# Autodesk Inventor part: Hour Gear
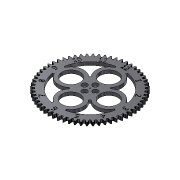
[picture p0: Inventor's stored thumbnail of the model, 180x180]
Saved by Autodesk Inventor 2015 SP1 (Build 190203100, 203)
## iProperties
Created: 2015-01
Part Number: Hour Gear
Material: Generic
Document SubType Name: Modeling
Designer: Steve Brooks
Density: 1 g/cm^3
Appearance: Machined 02
Author: Steve Brooks
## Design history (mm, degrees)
sketch "Sketch1"
  geometry: L1 (188.518, 97.087)-(187.786, 96.937); L2 (187.786, 96.937)-(187.059, 96.777); L3 (187.059, 96.777)-(183.576, 103.613); L4 (183.576, 103.613)-(184.133, 104.108); L5 (184.133, 104.108)-(184.684, 104.611); L6 (184.684, 104.611)-(185.773, 105.645); L7 (185.773, 105.645)-(187.893, 107.812); L8 (187.893, 107.812)-(189.944, 110.099); L9 (189.944, 110.099)-(191.929, 112.496); L10 (191.929, 112.496)-(193.85, 114.995); L11 (193.85, 114.995)-(195.708, 117.588); L12 (195.708, 117.588)-(194.272, 120.077); L13 (194.272, 120.077)-(191.096, 119.764); L14 (191.096, 119.764)-(187.971, 119.349); L15 (187.971, 119.349)-(184.903, 118.829); L16 (184.903, 118.829)-(181.898, 118.197); L17 (181.898, 118.197)-(178.96, 117.444); L18 (178.96, 117.444)-(177.52, 117.019); L19 (177.52, 117.019)-(176.809, 116.792); L20 (176.809, 116.792)-(176.102, 116.557); L21 (176.102, 116.557)-(171.923, 122.992); L22 (171.923, 122.992)-(172.426, 123.542); L23 (172.426, 123.542)-(172.922, 124.1); L24 (172.922, 124.1)-(173.896, 125.242); L25 (173.896, 125.242)-(175.778, 127.619); L26 (175.778, 127.619)-(177.579, 130.108); L27 (177.579, 130.108)-(179.302, 132.699); L28 (179.302, 132.699)-(180.951, 135.385); L29 (180.951, 135.385)-(182.529, 138.159); L30 (182.529, 138.159)-(180.84, 140.483); L31 (180.84, 140.483)-(177.714, 139.841); L32 (177.714, 139.841)-(174.651, 139.101); L33 (174.651, 139.101)-(171.654, 138.263); L34 (171.654, 138.263)-(168.73, 137.321); L35 (168.73, 137.321)-(165.888, 136.265); L36 (165.888, 136.265)-(164.501, 135.691); L37 (164.501, 135.691)-(163.816, 135.392); L38 (163.816, 135.392)-(163.138, 135.084); L39 (163.138, 135.084)-(158.309, 141.047); L40 (158.309, 141.047)-(158.752, 141.646); L41 (158.752, 141.646)-(159.187, 142.253); L42 (159.187, 142.253)-(160.037, 143.49); L43 (160.037, 143.49)-(161.66, 146.052); L44 (161.66, 146.052)-(163.19, 148.715); L45 (163.19, 148.715)-(164.633, 151.473); L46 (164.633, 151.473)-(165.993, 154.316); L47 (165.993, 154.316)-(167.271, 157.239); L48 (167.271, 157.239)-(165.35, 159.375); L49 (165.35, 159.375)-(162.307, 158.408); L50 (162.307, 158.408)-(159.338, 157.353); L51 (159.338, 157.353)-(156.445, 156.206); L52 (156.445, 156.206)-(153.635, 154.963); L53 (153.635, 154.963)-(150.919, 153.616); L54 (150.919, 153.616)-(149.6, 152.901); L55 (149.6, 152.901)-(148.95, 152.531); L56 (148.95, 152.531)-(148.309, 152.154); L57 (148.309, 152.154)-(142.883, 157.58); L58 (142.883, 157.58)-(143.26, 158.222); L59 (143.26, 158.222)-(143.63, 158.871); L60 (143.63, 158.871)-(144.345, 160.191); L61 (144.345, 160.191)-(145.692, 162.907); L62 (145.692, 162.907)-(146.935, 165.716); L63 (146.935, 165.716)-(148.082, 168.609); L64 (148.082, 168.609)-(149.137, 171.578)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
  constraints: 2164 end point, 4 midpoint
extrude "Extrusion1" new body sketch "Sketch1" distance "d0" = 18; taper "d1" = 0 deg
sketch "Sketch3"
  geometry: L1 (-35.849, 170.975)-(-40.492, 179.017); L2 (21.576, 170.975)-(26.219, 179.017); L3 (-175.977, -26.577)-(-184.019, -31.22); L4 (-175.977, 30.847)-(-184.019, 35.49); L5 (27.368, -164.816)-(32.368, -173.477); L6 (-41.641, -164.816)-(-46.641, -173.477); L7 (160.526, 33.336)-(169.186, 38.336); L8 (160.526, -29.066)-(169.186, -34.066); L9 (-7.136, 2.135)-(-7.136, -182.716); L10 (-5.7, 235.53)-(-8.573, 235.53) reference; L11 (-240.532, 3.571)-(-240.532, 0.699) reference; L12 (-8.573, -231.261)-(-5.7, -231.261) reference; L13 (226.259, 0.699)-(226.259, 3.571) reference; L14 (-240.532, 2.135)-(226.259, 2.135); L15 (-7.136, 235.53)-(-7.136, -231.261); C1 r 50 at (-7.136, 107.135); C2 r 50 at (-112.136, 2.135); C3 r 50 at (-7.136, -103.911); C4 r 50 at (97.864, 2.135); A1 r 70 centre (-7.136, 107.135) between (-35.849, 170.975) and (21.576, 170.975); A2 r 105 centre (-7.136, 2.135) between (-7.136, 107.135) and (97.864, 2.135); A3 r 70 centre (-112.136, 2.135) between (-175.977, -26.577) and (-175.977, 30.847); A4 r 70 centre (-7.136, -103.911) between (27.368, -164.816) and (-41.641, -164.816); A5 r 70 centre (97.864, 2.135) between (160.526, 33.336) and (160.526, -29.066); A6 r 180 centre (-7.136, 2.135) between (-40.492, 179.017) and (-184.019, 35.49); A7 r 180 centre (-7.136, 2.135) between (169.186, 38.336) and (26.219, 179.017); A8 r 180 centre (-7.136, 2.135) between (-184.019, -31.22) and (-46.641, -173.477); A9 r 180 centre (-7.136, 2.135) between (32.368, -173.477) and (169.186, -34.066); A10 r 80 centre (-7.136, 2.135) between (-60.454, 61.778) and (-66.779, 55.452); A11 r 80 centre (-7.136, 2.135) between (52.507, 55.452) and (46.181, 61.778); A12 r 80 centre (-7.136, 2.135) between (-66.779, -51.182) and (-59.943, -57.96); A13 r 80 centre (-7.136, 2.135) between (45.67, -57.96) and (52.507, -51.182); 4 further points
  constraints: 35 point on circle, 22 end point, 17 centre point, 13 midpoint, 12 equal radius, 10 coincident, 6 equal length, 3 vertical alignment, 2 horizontal alignment, 2 vertical
  dimensions: "d11" = 20 radial gap between concentric circles of C1 A1; "d13" = 210 diameter of A2; "d20" = 100 diameter of C1; "d26" = 60 deg angle of L6 L5; "d27" = 30 deg angle of L9 L5 (derived); "d28" = 10 distance of L8.start L8.end; "d29" = 60 deg angle of L4 L3; "d30" = 60 deg angle of L7 L8; "d31" = 60 deg angle of L1 L2; "d32" = 180 radius of A8; "d49" = 30 deg angle of L14 L7 (derived); "d50" = 30 deg angle of L15 L1 (derived); "d51" = 30 deg angle of L4 L14 (derived); "d56" = 80 radius of A12
extrude "Extrusion2" cut sketch "Sketch3" stored distance "d24" = 10; taper "d25" = 0 deg
sketch "Sketch4"
  geometry: C1 r 3 at (-7.136, 2.135); A1 r 180 centre (-7.136, 2.135) between (32.368, -173.477) and (169.186, -34.066) reference
  constraints: 1 centre point, 1 coincident
  dimensions: "d36" = 6 diameter of C1
extrude "Extrusion3" cut sketch "Sketch4" stored distance "d34" = 10; taper "d35" = 0 deg
sketch "Sketch6"
  geometry: C1 r 3 at (-7.136, 2.135) reference; C2 r 15 at (22.864, 2.135); C3 r 15 at (-7.136, 32.135); C4 r 15 at (-37.136, 2.135); C5 r 15 at (-7.136, -27.865)
  constraints: 4 centre point, 1 horizontal alignment, 9 other
  dimensions: "d60" = 30 distance of C2.centre C1.centre; "d61" = 30 diameter of C2; "d64" = 360 deg dimension on C1.centre C2.centre (derived)
extrude "Extrusion4" cut sketch "Sketch6" stored distance "d66" = 10; taper "d67" = 0 deg
sketch "Sketch5" dims "d74" = 395
  geometry: L1 (-5.7, 235.53)-(-8.573, 235.53) reference; L2 (-7.136, 2.135)-(-7.136, 235.53); L3 (-7.136, 2.135)-(-123.834, 204.261); L4 (-7.136, 2.135)-(-209.263, 118.833); L5 (-7.136, 2.135)-(-240.532, 2.135); L6 (-7.136, 2.135)-(-209.263, -114.563); L7 (-7.136, 2.135)-(-123.834, -199.991); L8 (-7.136, 2.135)-(-7.136, -231.261); L9 (-7.136, 2.135)-(109.561, -199.991); L10 (-7.136, 2.135)-(194.99, -114.563); L11 (-7.136, 2.135)-(226.259, 2.135); L12 (-7.136, 2.135)-(194.99, 118.833); L13 (-7.136, 2.135)-(109.561, 204.261); L14 (-27.447, 216.054)-(13.174, 216.054); L15 (13.174, 216.054)-(13.174, 183.216); L16 (13.174, 183.216)-(-27.447, 183.216); L17 (-27.447, 183.216)-(-27.447, 216.054); L18 (-27.447, 216.054)-(13.174, 183.216); L19 (-27.447, 183.216)-(13.174, 216.054); L20 (89.753, 188.521)-(105.834, 179.237); L21 (105.834, 179.237)-(93.256, 157.451); L22 (93.256, 157.451)-(77.175, 166.735); L23 (77.175, 166.735)-(89.753, 188.521); L24 (6.51, -178.474)-(6.51, -211.312); L25 (6.51, -211.312)-(-20.782, -211.312); L26 (-20.782, -211.312)-(-20.782, -178.474); L27 (-20.782, -178.474)-(6.51, -178.474); L28 (-191.189, -18.605)-(-215.9, -18.605); L29 (-215.9, -18.605)-(-215.9, 22.875); L30 (-215.9, 22.875)-(-191.189, 22.875); L31 (-191.189, 22.875)-(-191.189, -18.605); L32 (100.529, -144.211)-(116.435, -171.76); L33 (116.435, -171.76)-(81.676, -191.828); L34 (81.676, -191.828)-(65.77, -164.279); L35 (65.77, -164.279)-(100.529, -144.211); L36 (-78.486, -164.517)-(-94.809, -192.788); L37 (-94.809, -192.788)-(-132.109, -171.253); L38 (-132.109, -171.253)-(-115.787, -142.982); L39 (-115.787, -142.982)-(-78.486, -164.517); L40 (-153.296, -104.916)-(-181.735, -121.335); L41 (-181.735, -121.335)-(-201.363, -87.337); L42 (-201.363, -87.337)-(-172.925, -70.918); L43 (-172.925, -70.918)-(-153.296, -104.916); L44 (161.336, -71.982)-(184.753, -85.502); L45 (184.753, -85.502)-(164.704, -120.228); L46 (164.704, -120.228)-(141.287, -106.708); L47 (141.287, -106.708)-(161.336, -71.982); L48 (139.308, 108.788)-(167.747, 125.207); L49 (167.747, 125.207)-(186.889, 92.052); L50 (186.889, 92.052)-(158.45, 75.633); L51 (158.45, 75.633)-(139.308, 108.788); L52 (-98.936, 161.137)-(-112.837, 185.213); L53 (-112.837, 185.213)-(-112.837, 185.213); L54 (-112.837, 185.213)-(-98.936, 161.137); L55 (-98.936, 161.137)-(-98.936, 161.137); L56 (175.919, 22.141)-(202.776, 22.141); L57 (202.776, 22.141)-(202.776, -17.871); L58 (202.776, -17.871)-(175.919, -17.871); L59 (175.919, -17.871)-(175.919, 22.141); L60 (-171.067, 96.78)-(-185.286, 104.99); L61 (-185.286, 104.99)-(-185.286, 104.99); L62 (-185.286, 104.99)-(-171.067, 96.78); L63 (-171.067, 96.78)-(-171.067, 96.78); C1 r 3 at (-7.136, 2.135) reference; C2 r 3 at (-7.136, 2.135) reference; A1 r 80 centre (-7.136, 2.135) between (45.67, -57.96) and (52.507, -51.182) reference; A2 r 180 centre (-7.136, 2.135) between (-184.019, -31.22) and (-46.641, -173.477) reference; 48 further points
  constraints: 36 midpoint, 28 end point, 26 point on line, 4 coincident, 1 point on circle, 87 other
  dimensions: "d70" = 360 deg dimension on C1.centre L2.end (derived); "d77" = 360 deg dimension on C1.centre point (91.614, 173.175) (derived)
extrude "Extrusion5" cut sketch "Sketch5" distance "d72" = 2; taper "d73" = 0 deg
body "Solid1"
other parameters: "d18" = 60 deg, "d19" = 30 deg (derived)
